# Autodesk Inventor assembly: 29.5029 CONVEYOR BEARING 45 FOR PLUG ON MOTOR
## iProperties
Created: 2007-04
Part Number: 29.5029 CONVEYOR BEARING 45 FOR PLUG ON MOTOR
Document SubType Name: Assembly
Designer: Andy Moles
Author: Andy Moles
